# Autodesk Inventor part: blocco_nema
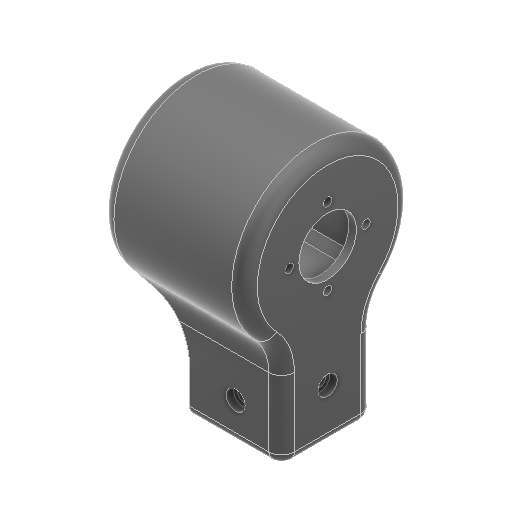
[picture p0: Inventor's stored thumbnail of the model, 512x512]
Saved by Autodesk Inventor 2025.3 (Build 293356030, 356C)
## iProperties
Created: 2026-03
Part Number: blocco_nema
Material: Plastica ABS
Document SubType Name: Modeling
Designer: R5800u
Density: 1.06 g/cm^3
Appearance: Liscia - Nero
Author: R5800u
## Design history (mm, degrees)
sketch "Schizzo1"
  geometry: L1 (18, 18)-(-18, 18); L2 (-18, 18)-(-18, -18); L3 (-18, -18)-(18, -18); L4 (18, -18)-(18, 18); L5 (18, 18)-(-18, -18); L6 (-18, 18)-(18, -18); L7 (10, 10)-(-10, 10); L8 (-10, 10)-(-10, -10); L9 (-10, -10)-(10, -10); L10 (10, -10)-(10, 10); L11 (10, 10)-(-10, -10); L12 (-10, 10)-(10, -10); 1 further point
  constraints: 24 end point, 4 midpoint, 4 parallel, 2 horizontal, 2 perpendicular
  dimensions: "d0" = 36 distance of L3.end L2.end; "d1" = 36 distance of L2.end L1.end; "d2" = 20 distance of L9.end L8.end; "d3" = 20 distance of L8.end L7.end
extrude "Estrusione1" new body sketch "Schizzo1" distance "d4" = 40; taper "d5" = 0 deg
sketch "Schizzo2" dims "d6" = 65
  geometry: L1 (40, -18)-(40, 18) reference; L2 (40, 0)-(87.596, 0); L3 (88.06, 21)-(46.06, 21); L4 (46.06, 21)-(46.06, -21); L5 (46.06, -21)-(88.06, -21); L6 (88.06, -21)-(88.06, 21); L7 (88.06, 21)-(46.06, -21); L8 (46.06, 21)-(88.06, -21); 3 further points
  constraints: 14 end point, 3 midpoint, 2 horizontal, 2 parallel, 1 perpendicular, 1 point on line, 3 other
  dimensions: "d7" = 42 distance of L5.end L4.end; "d8" = 42 distance of L4.end L3.end
extrude "Estrusione2" join sketch "Schizzo2" stored distance "d9" = 36; taper "d10" = 0 deg
sketch "Schizzo3"
  geometry: L1 (-3, 88.06)-(39, 88.06) reference; L2 (39, 88.06)-(39, 46.06) reference; L3 (39, 46.06)-(-3, 46.06) reference; L4 (-3, 46.06)-(-3, 88.06) reference; L5 (0, 0)-(36, 0) reference; L6 (36, 0)-(36, 40) reference; L7 (0, 0)-(0, 40) reference; A1 r 32.5 centre (18, 67.06) between (36, 40) and (0, 40) reference; 3 further points
  constraints: 1 coincident, 3 other
extrude "Estrusione3" join sketch "Schizzo3" distance "d11" = 20; taper "d12" = 0 deg
fillet "Raccordo1" dims "d13" = 20
sketch "Schizzo4"
  geometry: L1 (-3, 88.06)-(39, 88.06) reference; L2 (39, 88.06)-(39, 46.06) reference; L3 (39, 46.06)-(-3, 46.06) reference; L4 (-3, 46.06)-(-3, 88.06) reference; L5 (0, 0)-(36, 0) reference; L6 (36, 0)-(36, 30.835) reference; L7 (0, 0)-(0, 30.835) reference; C1 r 11.25 at (18, 67.06); C2 r 1.621 at (18, 82.06) reference; C3 r 1.621 at (3, 67.06) reference; C4 r 1.621 at (18, 52.06) reference; C5 r 1.621 at (33, 67.06) reference; A1 r 20 centre (56, 30.835) between (41.524, 44.635) and (36, 30.835) reference; A2 r 32.5 centre (18, 67.06) between (41.524, 44.635) and (-5.524, 44.635) reference; A3 r 20 centre (-20, 30.835) between (0, 30.835) and (-5.524, 44.635) reference; 1 further point
  constraints: 1 centre point, 1 coincident
  dimensions: "d14" = 22.5 diameter of C1
  node "Linea chiusa proiettata2"
  node "Riferimento1"
  node "Riferimento2"
  node "Riferimento3"
  node "Riferimento4"
node "Piano di lavoro1"
extrude "Estrusione4" join sketch "Schizzo4" stored distance "d15" = 20; taper "d16" = 0 deg
fillet "Raccordo2" dims "d17" = 5
chamfer "Smusso3" distance "d24" = 3; stored, may be unused: second distance "d25" = 2, angle "d26" = 45 deg
fillet "Raccordo3" dims "d27" = 4
sketch "Schizzo5"
  geometry: L1 (22.037, -30.835)-(22.037, -15.835)
  constraints: 2 end point, 1 vertical
  dimensions: "d28" = 15 distance of L1.start L1.end
hole "Foro1" sketch "Schizzo5" at (22.037, -15.835) diameter "d29" = 4.3; stored, may be unused: countersink angle "d33" = 90 deg, drill point angle "d35" = 118 deg; dims "d30" = 6, "d31" = 7.5, "d32" = 3, "d34" = 8
sketch "Schizzo6"
  geometry: C1 r 2.15 at (13, -15.835) reference; 2 further points
  constraints: 1 coincident
hole "Foro2" sketch "Schizzo6" at (13, -15.835) diameter "d36" = 4.3; stored, may be unused: countersink angle "d40" = 90 deg, drill point angle "d42" = 118 deg; dims "d37" = 6, "d38" = 7.5, "d39" = 3, "d41" = 8
sketch "Schizzo7"
  geometry: L1 (0, -67.06)-(0, -47.06)
  constraints: 2 end point, 1 vertical
  dimensions: "d43" = 20 distance of L1.start L1.end
hole "Foro3" sketch "Schizzo7" at (0, -47.06) diameter "d44" = 4.3; stored, may be unused: countersink angle "d48" = 90 deg, drill point angle "d50" = 118 deg; dims "d45" = 6, "d46" = 7.5, "d47" = 3, "d49" = 8
node "Solido1"
node "Linea chiusa proiettata1"
